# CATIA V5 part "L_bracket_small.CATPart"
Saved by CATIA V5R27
Part number: 47065T845_Silver Corner Bracket
Revision: ANY
Definition: UNKNOWN
Nomenclature: 47065T845_Silver Corner Bracket
Source: Unknown
Bounding box of the stored display mesh (mm): x 0 to 38.1, y 0 to 38.1, z -16.637 to 16.637
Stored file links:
  \\triton.meca.polymtl.ca\usagers\zaoue\profiles\Desktop\varm_ass\structure prismatique\L_bracket_small.CATPart
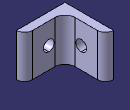
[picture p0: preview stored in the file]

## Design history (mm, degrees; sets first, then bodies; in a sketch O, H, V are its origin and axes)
Body1 "Cut-Extrude2" (main body)
  Solid1: solid without history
